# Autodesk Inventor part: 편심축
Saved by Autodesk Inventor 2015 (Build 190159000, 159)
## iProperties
Created: 2025-08
Part Number: 편심축
Material: 일반
Document SubType Name: Modeling
Designer: USER
Density: 1 g/cm^3
Appearance: 기본값
Author: USER
Author: jhkim
Creation Date: 2025-08-05
Sending System: Autodesk Inventor 2026
Preprocessor: ST-DEVELOPER v20.1
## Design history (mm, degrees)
node "편심축1"
node "솔리드1"
node "기준1"
